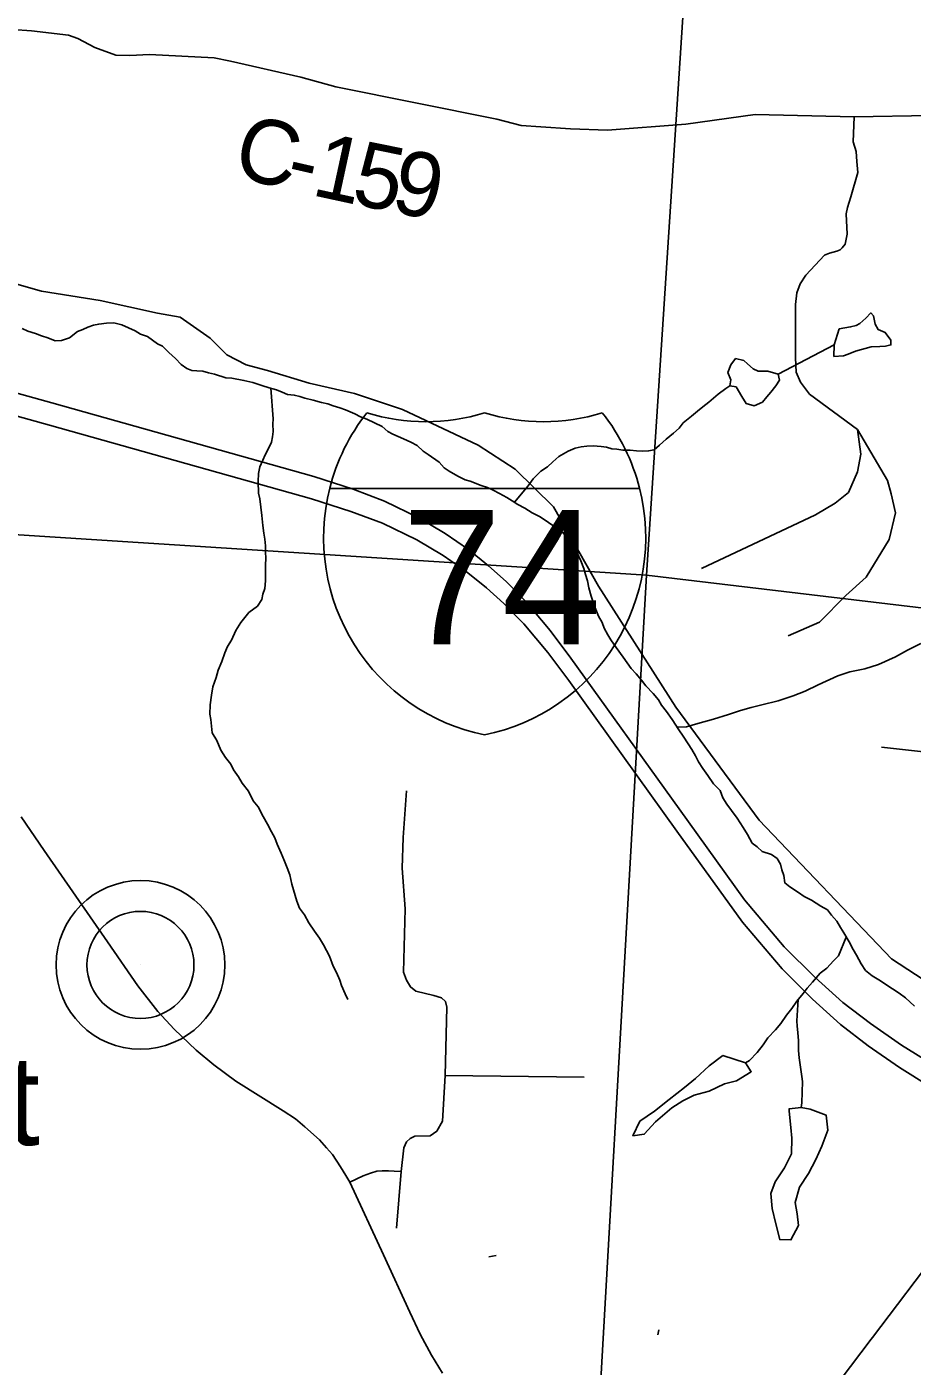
# Model space of a CAD drawing. Extents: x 0 to 34, y 0 to 22.
# Drawn here: x 6.66 to 7.441, y 15.353 to 16.534 of the extents above; entities that cross this region are included whole.
import ezdxf

# ---------------------------------------------------------------- set-up
doc = ezdxf.new("R2010")
doc.units = 0
for name, color, linetype in [('GM_X_County_Road', 7, 'Continuous'), ('GM_X_County_Road_Text', 7, 'Continuous'), ('GM_X_Interstate_Location', 7, 'Continuous'), ('GM_X_Interstate_Route', 7, 'Continuous'), ('GM_X_Interstate_Shield', 7, 'Continuous'), ('GM_X_Minor_Lake', 7, 'Continuous'), ('GM_X_Minor_River', 7, 'Continuous'), ('GM_X_Section', 7, 'Continuous'), ('GM_X_Township_Road', 7, 'Continuous'), ('GM_X_Unincorporated', 7, 'Continuous'), ('GM_X_Unincorporated_Location', 7, 'Continuous'), ('GM_X_Unincorporated_Text', 7, 'Continuous'), ('GM_X_US_Route', 7, 'Continuous')]:
    doc.layers.add(name, color=color, linetype=linetype)

msp = doc.modelspace()

# ---------------------------------------------------------------- linework, layer by layer
at = {"layer": 'GM_X_County_Road'}
for points in [[(6.6469, 16.5319), (6.6639, 16.5306), (6.6964, 16.5269), (6.7046, 16.5239), (6.7195, 16.5159), (6.7383, 16.5092), (6.7504, 16.5088), (6.7679, 16.5097), (6.825, 16.5068), (6.8393, 16.504), (6.9014, 16.4899), (6.9322, 16.4813), (7.0744, 16.4527), (7.0956, 16.4472), (7.1132, 16.446), (7.1392, 16.4442), (7.172, 16.443), (7.241, 16.4485), (7.3021, 16.4569), (7.3896, 16.4548), (7.4569, 16.456)], [(6.6266, 16.314), (6.6726, 16.3011), (6.7242, 16.2928), (6.7748, 16.2818), (6.795, 16.2781), (6.8213, 16.2597), (6.836, 16.245), (6.853, 16.2362), (6.8719, 16.2311), (6.9087, 16.2201), (6.9487, 16.2109), (6.9911, 16.1966), (7.0578, 16.1653), (7.0904, 16.144), (7.1244, 16.1109), (7.164, 16.0409), (7.2321, 15.9341), (7.3057, 15.8346), (7.4226, 15.7122), (7.514, 15.6525)], [(6.6545, 15.8376), (6.675, 15.8077), (6.7307, 15.7272), (6.7575, 15.6884), (6.7751, 15.6657), (6.7895, 15.6502), (6.8091, 15.6317), (6.8247, 15.6188), (6.8439, 15.6044), (6.8858, 15.5783), (6.8967, 15.571), (6.905, 15.5642), (6.9178, 15.5526), (6.924, 15.5456), (6.9292, 15.5396), (6.9364, 15.5287), (6.941, 15.5213), (6.9445, 15.5153), (6.9742, 15.4511), (6.9975, 15.4006), (7.0066, 15.3811), (7.0165, 15.3628), (7.0264, 15.3468)]]:
    msp.add_lwpolyline(points, dxfattribs=at)
at = {"layer": 'GM_X_Interstate_Route'}
for points in [[(6.6042, 16.2241), (6.6816, 16.2026), (6.9128, 16.1375), (6.9475, 16.1265), (6.9753, 16.116), (7.0056, 16.1013), (7.0288, 16.0875), (7.0492, 16.0734), (7.067, 16.059), (7.0824, 16.0451), (7.0999, 16.0274), (7.1212, 16.0019), (7.1396, 15.9774), (7.235, 15.8445), (7.2929, 15.7642), (7.3278, 15.7229), (7.3548, 15.6962), (7.3795, 15.6738), (7.4039, 15.6552), (7.4313, 15.6361), (7.4583, 15.6194)], [(6.6023, 16.2045), (6.6797, 16.183), (6.9109, 16.1179), (6.9456, 16.1069), (6.9734, 16.0964), (7.0037, 16.0817), (7.0269, 16.0679), (7.0473, 16.0538), (7.0651, 16.0394), (7.0804, 16.0256), (7.098, 16.0078), (7.1193, 15.9823), (7.1377, 15.9578), (7.2331, 15.8249), (7.291, 15.7446), (7.3259, 15.7034), (7.3528, 15.6766), (7.3776, 15.6542), (7.402, 15.6356), (7.4294, 15.6165), (7.4564, 15.5998)]]:
    msp.add_lwpolyline(points, dxfattribs=at)
at = {"layer": 'GM_X_Interstate_Shield'}
for p, q in [((6.9269, 16.1272), (7.2001, 16.1272)), ((7.2001, 16.1272), (6.9269, 16.1272)), ((7.2001, 16.1272), (6.9269, 16.1272))]:
    msp.add_line(p, q, dxfattribs=at)
for centre, start, end in [((7.099, 16.0837), 141.669, 165.8066), ((7.0116, 16.3636), 253.0091, 286.9909), ((7.1154, 16.3636), 253.0091, 286.9909), ((7.028, 16.0837), 14.1934, 38.331), ((7.099, 16.0837), 165.8066, 258.463), ((7.028, 16.0837), 281.537, 14.1934)]:
    msp.add_arc(centre, 0.1776, start, end, dxfattribs=at)
at = {"layer": 'GM_X_Minor_Lake'}
for p, q in [((7.2737, 15.6271), (7.2937, 15.6204)), ((7.3323, 15.5801), (7.3429, 15.5812))]:
    msp.add_line(p, q, dxfattribs=at)
for points in [[(7.3719, 16.2539), (7.3764, 16.2678), (7.3864, 16.2695), (7.3913, 16.2708), (7.3944, 16.2727), (7.3999, 16.2774), (7.4042, 16.2819), (7.4067, 16.2792), (7.4081, 16.2719), (7.4106, 16.2673), (7.417, 16.2645), (7.4218, 16.2579), (7.422, 16.2537), (7.4171, 16.2527), (7.4121, 16.2524), (7.4045, 16.2519)], [(7.4045, 16.2519), (7.3907, 16.2481), (7.3842, 16.2456), (7.38, 16.2442), (7.3716, 16.2436), (7.3719, 16.2539)], [(7.2806, 16.2362), (7.2781, 16.2294), (7.2807, 16.223), (7.2799, 16.2177)], [(7.2799, 16.2177), (7.2854, 16.2167), (7.2905, 16.2082), (7.2941, 16.202), (7.3013, 16.1999), (7.3086, 16.2031), (7.3125, 16.208), (7.3161, 16.2121), (7.3204, 16.2176), (7.3236, 16.2225), (7.3226, 16.2278), (7.3135, 16.2304), (7.3048, 16.2306), (7.3003, 16.2326), (7.2954, 16.2369), (7.2921, 16.24), (7.2849, 16.2417), (7.2806, 16.2362)], [(7.2937, 15.6204), (7.2988, 15.6127), (7.2857, 15.6047), (7.275, 15.602), (7.2615, 15.5955), (7.2485, 15.592), (7.2385, 15.587), (7.2288, 15.5808), (7.2144, 15.5686), (7.2043, 15.5575), (7.1944, 15.5562), (7.2004, 15.569), (7.2135, 15.5778), (7.2264, 15.5881), (7.2399, 15.5987), (7.2496, 15.6068), (7.2617, 15.6179), (7.2737, 15.6271)], [(7.3429, 15.5812), (7.3508, 15.5798), (7.3647, 15.5745), (7.3662, 15.5612), (7.3609, 15.5469), (7.3557, 15.5353), (7.3493, 15.5229), (7.3414, 15.511), (7.3376, 15.4974), (7.3392, 15.4875), (7.3405, 15.4772), (7.3337, 15.4644), (7.3238, 15.4647), (7.3204, 15.4785), (7.3173, 15.4922), (7.3161, 15.5052), (7.3198, 15.5157), (7.3281, 15.528), (7.3342, 15.5404), (7.3345, 15.5541), (7.3336, 15.5636), (7.3321, 15.578), (7.3323, 15.5802)]]:
    msp.add_lwpolyline(points, dxfattribs=at)
at = {"layer": 'GM_X_Minor_River'}
for points in [[(6.6726, 16.2616), (6.6674, 16.2637), (6.6606, 16.2658), (6.6554, 16.2683)], [(7.2239, 15.9303), (7.2195, 15.9361), (7.217, 15.9407), (7.2123, 15.9462), (7.2057, 15.9529), (7.202, 15.958), (7.1973, 15.9635), (7.1929, 15.9682), (7.1856, 15.9783), (7.1795, 15.9869), (7.1748, 15.9935), (7.1723, 15.9981), (7.1691, 16.0039), (7.1673, 16.0089), (7.1641, 16.0144), (7.1616, 16.0202), (7.1599, 16.0248), (7.1575, 16.0321), (7.1555, 16.0394), (7.1542, 16.0455), (7.1525, 16.0512), (7.1511, 16.0566), (7.1483, 16.0632), (7.1448, 16.0709), (7.1405, 16.0775), (7.1365, 16.083), (7.1321, 16.0884), (7.1199, 16.0972), (7.1124, 16.102), (7.1054, 16.1057), (7.099, 16.1097), (7.0927, 16.113), (7.0879, 16.1162), (7.083, 16.119), (7.0767, 16.1226), (7.0711, 16.1255), (7.0659, 16.1279), (7.0606, 16.1297), (7.0509, 16.1334), (7.0464, 16.1347), (7.04, 16.138), (7.0322, 16.1424), (7.0277, 16.1452), (7.0234, 16.1503), (7.0137, 16.1571), (7.0093, 16.1599), (7.0041, 16.165), (6.9985, 16.1679), (6.9918, 16.1708), (6.9824, 16.1749), (6.978, 16.1773), (6.9732, 16.1817), (6.9597, 16.1882), (6.9541, 16.1903), (6.9489, 16.1928), (6.9407, 16.1965), (6.9358, 16.1982), (6.9298, 16.1999), (6.9253, 16.2016), (6.9196, 16.2029), (6.9121, 16.2051), (6.905, 16.2068), (6.9004, 16.2081), (6.8956, 16.2095), (6.8895, 16.21), (6.885, 16.2121), (6.8798, 16.2142), (6.8734, 16.2159), (6.867, 16.218), (6.8591, 16.2206), (6.8512, 16.2224), (6.8406, 16.2243), (6.8353, 16.2248), (6.8252, 16.2278), (6.8199, 16.2292), (6.815, 16.2305), (6.8097, 16.2307), (6.8052, 16.2312), (6.8007, 16.2329), (6.7959, 16.2365), (6.7907, 16.2416), (6.7849, 16.2471), (6.7793, 16.2526), (6.7749, 16.2547), (6.766, 16.2611), (6.76, 16.2632), (6.7551, 16.266), (6.7492, 16.2689), (6.7435, 16.2713), (6.7364, 16.2731), (6.7299, 16.2729), (6.7231, 16.272), (6.7185, 16.2711), (6.7135, 16.2693), (6.7089, 16.2672), (6.7042, 16.2655), (6.6972, 16.26), (6.6903, 16.2576), (6.6846, 16.2574), (6.6782, 16.2599), (6.6726, 16.2616)], [(7.3226, 16.2278), (7.3719, 16.2539)], [(6.8749, 16.2155), (6.877, 16.1884), (6.8768, 16.1839), (6.877, 16.1774), (6.8764, 16.1725), (6.8755, 16.168), (6.8723, 16.1613), (6.8698, 16.1568), (6.8678, 16.1519), (6.8653, 16.1463), (6.8639, 16.1403), (6.8637, 16.1331), (6.8641, 16.1228), (6.8651, 16.1178), (6.866, 16.1106), (6.8669, 16.1033), (6.8677, 16.0945), (6.8686, 16.0877), (6.8695, 16.0823), (6.8701, 16.0766), (6.8703, 16.0705), (6.8705, 16.066), (6.8703, 16.0591), (6.8703, 16.0504), (6.8702, 16.0455), (6.8696, 16.039), (6.8679, 16.0338), (6.867, 16.0292), (6.863, 16.0233), (6.8556, 16.0178), (6.852, 16.0134), (6.8484, 16.009), (6.844, 16.0019), (6.8403, 15.9933), (6.8367, 15.9877), (6.8342, 15.9821), (6.8317, 15.9746), (6.8284, 15.9667), (6.8266, 15.9603), (6.8237, 15.9521), (6.8227, 15.9449), (6.8213, 15.9362), (6.821, 15.9279), (6.8219, 15.9233), (6.8231, 15.9115), (6.8274, 15.9049), (6.8309, 15.8964), (6.8348, 15.8898), (6.8396, 15.8839), (6.8421, 15.8789), (6.8464, 15.8727), (6.8496, 15.8672), (6.8551, 15.8602), (6.8594, 15.8517), (6.8637, 15.8462), (6.868, 15.8377), (6.8719, 15.8311), (6.8755, 15.8242), (6.8784, 15.8191), (6.8804, 15.8134), (6.884, 15.8053), (6.8871, 15.7983), (6.8892, 15.7926), (6.8917, 15.7864), (6.8933, 15.778), (6.8977, 15.763), (6.9001, 15.7568), (6.9045, 15.751), (6.9084, 15.744), (6.9135, 15.7366), (6.9178, 15.7304), (6.9214, 15.7246), (6.9268, 15.7145), (6.9299, 15.7057), (6.9328, 15.7003), (6.9359, 15.6933), (6.9373, 15.6887), (6.9405, 15.6814), (6.9429, 15.6764)], [(7.0898, 16.1149), (7.102, 16.1294), (7.1064, 16.1357), (7.1131, 16.1423), (7.1189, 16.1462), (7.1236, 16.1506), (7.1291, 16.1554), (7.1372, 16.16), (7.1434, 16.1625), (7.1487, 16.1638), (7.1537, 16.1644), (7.1594, 16.1646), (7.1662, 16.164), (7.1711, 16.1634), (7.1756, 16.1621), (7.1802, 16.1616), (7.1855, 16.161), (7.1919, 16.1608), (7.1976, 16.1602), (7.2029, 16.16), (7.2082, 16.1602), (7.2132, 16.1612), (7.2179, 16.1652), (7.2238, 16.1707), (7.23, 16.1758), (7.2351, 16.1802), (7.2387, 16.185), (7.2461, 16.1908), (7.2512, 16.1952), (7.2559, 16.1992), (7.2613, 16.2032), (7.2695, 16.2102), (7.2762, 16.2153), (7.2799, 16.2177)], [(7.2332, 15.9167), (7.2416, 15.917), (7.2516, 15.9198), (7.2653, 15.9235), (7.2788, 15.9277), (7.2891, 15.9312), (7.2987, 15.934), (7.3082, 15.9364), (7.3224, 15.9398), (7.3358, 15.9443), (7.3462, 15.9482), (7.3577, 15.954), (7.3751, 15.9618), (7.3858, 15.9653), (7.3988, 15.968), (7.411, 15.9718), (7.4261, 15.9786), (7.4365, 15.9844), (7.4484, 15.9905)], [(7.4427, 15.6704), (7.4347, 15.6779), (7.4291, 15.6819), (7.4232, 15.6859), (7.4183, 15.6891), (7.4128, 15.6928), (7.4053, 15.6972), (7.3994, 15.702), (7.3958, 15.7078), (7.3915, 15.7155), (7.3887, 15.7206), (7.3851, 15.7271), (7.3804, 15.7353), (7.3775, 15.7399), (7.3743, 15.7454), (7.3696, 15.7508), (7.3659, 15.7555), (7.36, 15.7588), (7.3518, 15.764), (7.3455, 15.7673), (7.3403, 15.7709), (7.3328, 15.7757), (7.3284, 15.7792), (7.3275, 15.7857), (7.3258, 15.7907), (7.3244, 15.7957), (7.3215, 15.8008), (7.3167, 15.8043), (7.3085, 15.8069), (7.304, 15.8109), (7.2996, 15.8144), (7.2953, 15.8218), (7.2917, 15.828), (7.2863, 15.8362), (7.2812, 15.8432), (7.2772, 15.8486), (7.2736, 15.8541), (7.2712, 15.8606), (7.2653, 15.8665), (7.2603, 15.8739), (7.2559, 15.8801), (7.2523, 15.886), (7.2495, 15.8914), (7.2462, 15.8968), (7.243, 15.9019), (7.2387, 15.9085), (7.2347, 15.9143), (7.2289, 15.9232), (7.2239, 15.9303)], [(7.3826, 15.7315), (7.3756, 15.7149), (7.3712, 15.7105), (7.3653, 15.7039), (7.3595, 15.6995), (7.3527, 15.6918), (7.348, 15.6863), (7.3444, 15.6818), (7.3389, 15.6748), (7.3345, 15.6685), (7.3297, 15.6626), (7.3249, 15.6552), (7.3202, 15.6496), (7.3135, 15.6426), (7.3091, 15.6363), (7.3039, 15.6297), (7.2972, 15.6227), (7.2937, 15.6204)], [(7.3401, 15.6763), (7.339, 15.6577), (7.3393, 15.6528), (7.3398, 15.6474), (7.3403, 15.6398), (7.3404, 15.6314), (7.341, 15.625), (7.3422, 15.6166), (7.3434, 15.6085), (7.344, 15.604), (7.3434, 15.5854), (7.3429, 15.5812)], [(7.0673, 15.4495), (7.0738, 15.4507)], [(7.2164, 15.3805), (7.2173, 15.385)]]:
    msp.add_lwpolyline(points, dxfattribs=at)
at = {"layer": 'GM_X_Section'}
for points in [[(7.2711, 17.0443), (7.2064, 16.0507), (6.268, 16.1109), (6.3631, 17.0951)], [(7.2711, 17.0443), (8.3778, 16.9409), (8.2891, 15.9218), (7.2064, 16.0507)], [(7.2064, 16.0507), (7.1496, 15.0512), (6.1715, 15.1151), (6.268, 16.1109)], [(7.2064, 16.0507), (8.2891, 15.9218), (8.1869, 14.9268), (7.1496, 15.0512)]]:
    msp.add_lwpolyline(points, close=True, dxfattribs=at)
at = {"layer": 'GM_X_Township_Road'}
msp.add_line((7.0287, 15.6093), (7.1513, 15.608), dxfattribs=at)
for points in [[(7.3924, 16.1791), (7.35, 16.2103), (7.3421, 16.2209), (7.3384, 16.2297), (7.3378, 16.2424), (7.3377, 16.2894), (7.339, 16.2995), (7.342, 16.3076), (7.3469, 16.3153), (7.3633, 16.3328), (7.3677, 16.3345), (7.3742, 16.3363), (7.3771, 16.3374), (7.379, 16.3394), (7.3816, 16.3425), (7.3834, 16.3515), (7.3825, 16.3692), (7.3837, 16.375), (7.3867, 16.3844), (7.3929, 16.4057), (7.3919, 16.4154), (7.3913, 16.4242), (7.3887, 16.4327), (7.3896, 16.4548)], [(7.2547, 16.0564), (7.3555, 16.1039), (7.3728, 16.114), (7.3844, 16.1236), (7.3924, 16.1417), (7.3955, 16.1574), (7.3924, 16.1791)], [(7.3312, 15.997), (7.359, 16.0091), (7.3821, 16.0326), (7.4002, 16.0489), (7.4203, 16.0822), (7.426, 16.1055), (7.4223, 16.1225), (7.4189, 16.1342), (7.3924, 16.1791)], [(8.0238, 15.8195), (7.815, 15.8439), (7.7711, 15.8482), (7.7256, 15.8543), (7.6927, 15.8649), (7.6552, 15.8792), (7.6343, 15.8875), (7.6216, 15.8904), (7.6072, 15.892), (7.5152, 15.8909), (7.4901, 15.8905), (7.4137, 15.899)], [(6.9857, 15.4748), (6.99, 15.5247), (6.9923, 15.5455), (6.9947, 15.5508), (6.9979, 15.5537), (7.0019, 15.5559), (7.0154, 15.5561), (7.0212, 15.5603), (7.0264, 15.5692), (7.0287, 15.6093), (7.0303, 15.6697), (7.0289, 15.6745), (7.0254, 15.6779), (7.0187, 15.6799), (7.0029, 15.6836), (6.9982, 15.6875), (6.9946, 15.6935), (6.9919, 15.7004), (6.9934, 15.7564), (6.9909, 15.7921), (6.9917, 15.8193), (6.9947, 15.8603)], [(6.9445, 15.5153), (6.9564, 15.5208), (6.9627, 15.5233), (6.9685, 15.525), (6.9732, 15.5253), (6.9788, 15.5253), (6.9837, 15.5251), (6.99, 15.5247)], [(7.4044, 15.3767), (7.4056, 15.3783), (7.4654, 15.4571)], [(7.156, 15.1816), (7.3203, 15.2711), (7.327, 15.2762), (7.3312, 15.2804), (7.3398, 15.2914), (7.4044, 15.3767)]]:
    msp.add_lwpolyline(points, dxfattribs=at)
at = {"layer": 'GM_X_Unincorporated'}
for radius in [0.0744, 0.0472]:
    msp.add_circle((6.7599, 15.7069), radius, dxfattribs=at)
at = {"layer": 'GM_X_Unincorporated_Location'}
msp.add_line((6.7599, 15.7069), (6.7599, 15.7069), dxfattribs=at)
at = {"layer": 'GM_X_US_Route'}
msp.add_lwpolyline([(6.6023, 16.2045), (6.6797, 16.183), (6.9109, 16.1179), (6.9456, 16.1069), (6.9734, 16.0964), (7.0037, 16.0817), (7.0269, 16.0679), (7.0473, 16.0538), (7.0651, 16.0394), (7.0804, 16.0256), (7.098, 16.0078), (7.1193, 15.9823), (7.1377, 15.9578), (7.2331, 15.8249), (7.291, 15.7446), (7.3259, 15.7034), (7.3528, 15.6766), (7.3776, 15.6542), (7.402, 15.6356), (7.4294, 15.6165), (7.4564, 15.5998)], dxfattribs=at)

# ---------------------------------------------------------------- texts
at = {"layer": 'GM_X_County_Road_Text'}
for s, rotation, p in [('C', 345.8689, (6.8395, 16.4032)), ('1', 347.7727, (6.9095, 16.3861)), ('5', 348.5949, (6.9446, 16.3785)), ('9', 348.8436, (6.9792, 16.3715)), ('-', 347.0069, (6.886, 16.3915))]:
    msp.add_text(s, height=0.0568, rotation=rotation, dxfattribs=at).set_placement(p)
at = {"layer": 'GM_X_Interstate_Location'}
for s in ['-', '.', ',']:
    msp.add_text(s, height=0.000189, dxfattribs=at).set_placement((7.0635, 16.0517))
msp.add_text('74', height=0.000189, rotation=0, dxfattribs=at).set_placement((7.0248, 16.0125))
at = {"layer": 'GM_X_Interstate_Shield'}
msp.add_text('74', height=0.11837, dxfattribs=at).set_placement((6.9904, 15.9896))
at = {"layer": 'GM_X_Unincorporated_Text'}
msp.add_text('Dent', height=0.07898, rotation=0, dxfattribs=at).set_placement((6.4481, 15.548))

doc.saveas('drawing.dxf')
